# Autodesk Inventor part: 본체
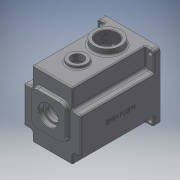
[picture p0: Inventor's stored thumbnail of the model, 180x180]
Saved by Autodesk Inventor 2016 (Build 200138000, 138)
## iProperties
Created: 2016-02
Part Number: 본체
Material: 알루미늄 6061
Document SubType Name: Modeling
Designer: mduedu
Density: 2.7 g/cm^3
Mass: 1348.73 g
Surface Area: 1142.22 cm^2
Volume: 499.531 cm^3
Appearance: 기본값
Author: mduedu
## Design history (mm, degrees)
sketch "스케치1"
  geometry: L1 (-47, -47)-(47, -47); L2 (47, -47)-(47, 63); L3 (47, 63)-(-47, 63); L4 (-47, 63)-(-47, -47); 2 further points
  constraints: 8 end point, 2 parallel, 1 horizontal, 1 midpoint, 1 perpendicular, 1 vertical alignment
  dimensions: "d0" = 94 distance of L2.end L3.end; "d155" = 110 distance of L1.end L2.end; "d156" = 47 distance from line of L1 point (0, 0)
extrude "돌출1" new body sketch "스케치1" distance "d2" = 130; taper "d3" = 0 deg
sketch "스케치3"
  geometry: C1 r 40 at (0, 0); 1 further point
  constraints: 1 centre point, 1 coincident
  dimensions: "d9" = 80 diameter of C1
extrude "돌출3" cut sketch "스케치3" distance "d11" = 121; taper "d12" = 0 deg
sketch "스케치4"
  geometry: C1 r 21 at (0, 11); 1 further point
  constraints: 1 centre point, 1 vertical alignment
  dimensions: "d13" = 21 radius of C1; "d15" = 11 distance of point (0, 0) C1.centre
extrude "돌출4" join sketch "스케치4" distance "d16" = 7; taper "d17" = 0 deg
sketch "스케치5"
  geometry: C1 r 15 at (0, -20); 1 further point
  constraints: 1 centre point, 1 vertical alignment
  dimensions: "d18" = 15 radius of C1; "d20" = 20 distance of point (0, 0) C1.centre
extrude "돌출5" join sketch "스케치5" distance "d21" = 7; taper "d22" = 0 deg
sketch "스케치6"
  geometry: L1 (-28, -17)-(28, -17); L2 (28, -17)-(28, 39); L3 (28, 39)-(-28, 39); L4 (-28, 39)-(-28, -17); L5 (-28, -17)-(28, 39); L6 (28, -17)-(-28, 39); C1 r 28 at (0, 11); A1 r 21 centre (0, 11) between (8.978, -7.984) and (-8.978, -7.984) reference; 1 further point
  constraints: 12 end point, 2 midpoint, 2 parallel, 2 tangent, 1 centre point, 1 coincident, 1 horizontal, 1 perpendicular
  dimensions: "d23" = 56 diameter of C1
extrude "돌출6" join sketch "스케치6" distance "d25" = 7; taper "d26" = -3 deg
hole "구멍1" diameter "d29" = 35; stored, may be unused: countersink angle "d33" = 90 deg, drill point angle "d35" = 0 deg; dims "d27" = 10, "d28" = 10, "d30" = 6, "d31" = 4, "d32" = 2, "d34" = 10
hole "구멍2" diameter "d38" = 22; stored, may be unused: countersink angle "d42" = 90 deg, drill point angle "d44" = 0 deg; dims "d36" = 10, "d37" = 10, "d39" = 6, "d40" = 4, "d41" = 2, "d43" = 7
hole "구멍3" diameter "d47" = 19; stored, may be unused: countersink angle "d51" = 90 deg, drill point angle "d53" = 0 deg; dims "d45" = 10, "d46" = 10, "d48" = 6, "d49" = 4, "d50" = 2, "d52" = 1
hole "구멍4" diameter "d56" = 32; stored, may be unused: countersink angle "d60" = 90 deg, drill point angle "d62" = 0 deg; dims "d57" = 6, "d58" = 4, "d59" = 2, "d61" = 8, "d220" = 10, "d221" = 10
hole "구멍5" diameter "d65" = 25; stored, may be unused: countersink angle "d69" = 90 deg, drill point angle "d71" = 0 deg; dims "d63" = 10, "d64" = 10, "d66" = 6, "d67" = 4, "d68" = 2, "d70" = 8
fillet "모깎기2" dims "d73" = 0.3
fillet "모깎기3" dims "d74" = 2
chamfer "모따기1" distance "d75" = 1; stored, may be unused: second distance "d76" = 2, angle "d77" = 45 deg
fillet "모깎기4" dims "d78" = 3
sketch "스케치16"
  geometry: L1 (-23, 32.726)-(23, 32.726); L2 (23, 32.726)-(23, 53); L3 (23, 53)-(-23, 53); L4 (-23, 53)-(-23, 32.726); L5 (-47, 63)-(47, 63) reference; 3 further points
  constraints: 8 end point, 2 parallel, 1 horizontal, 1 midpoint, 1 perpendicular, 1 vertical alignment, 2 other
  dimensions: "d160" = 46 distance of L2.end L3.end; "d163" = 10 distance between parallel lines of L3 L5
extrude "돌출15" cut sketch "스케치16" stored distance "d164" = 10; taper "d165" = 0 deg
fillet "모깎기5" dims "d79" = 2
fillet "모깎기15" dims "d166" = 5
sketch "스케치7"
  geometry: L1 (-23, 48)-(-23, 35.228) reference; L2 (23, 35.228)-(23, 48) reference; L3 (18, 53)-(-18, 53) reference; L4 (47, 63)-(47, -47) reference; L5 (47, -47)-(-47, -47) reference; L6 (-47, -47)-(-47, 63) reference; L7 (-47, 63)-(47, 63) reference; L8 (-26, 48)-(-26, 35.228); L9 (26, 35.228)-(26, 48); L10 (18, 56)-(-18, 56); C1 r 43 at (0, 0); A1 r 5 centre (-18, 48) between (-18, 53) and (-23, 48) reference; A2 r 5 centre (-28, 35.228) between (-24.889, 31.314) and (-23, 35.228) reference; A3 r 40 centre (0, 0) between (-24.889, 31.314) and (24.889, 31.314) reference; A4 r 5 centre (28, 35.228) between (23, 35.228) and (24.889, 31.314) reference; A5 r 5 centre (18, 48) between (23, 48) and (18, 53) reference; A6 r 8 centre (-18, 48) between (-18, 56) and (-26, 48); A7 r 2 centre (-28, 35.228) between (-26.756, 33.662) and (-26, 35.228); A8 r 43 centre (0, 0) between (-26.756, 33.662) and (26.756, 33.662); A9 r 2 centre (28, 35.228) between (26, 35.228) and (26.756, 33.662); A10 r 8 centre (18, 48) between (26, 48) and (18, 56); 1 further point
  constraints: 10 point on circle, 6 centre point, 6 end point, 1 coincident, 7 other
  dimensions: "d80" = 86 diameter of C1; "d167" = 3 distance between parallel lines of L3 L10
extrude "돌출7" cut sketch "스케치7" distance "d83" = 9; taper "d84" = 0 deg
sketch "스케치8" dims "d168" = 36
  geometry: L1 (-36, 4)-(-39.799, 4); L2 (-36, -4)-(-39.799, -4); A1 r 4 centre (-36, 0) between (-36, 4) and (-36, -4); A2 r 40 centre (0, 0) between (-24.889, 31.314) and (24.889, 31.314) reference; A3 r 40 centre (0, 0) between (-39.799, 4) and (-39.799, -4); 2 further points
  constraints: 5 point on circle, 4 end point, 2 centre point, 2 coincident, 2 horizontal alignment, 2 tangent, 1 horizontal, 1 parallel, 2 other
  dimensions: "d169" = 4 radius of A1
extrude "돌출9" join sketch "스케치8" stored distance "d89" = 9; taper "d90" = 0 deg
fillet "모깎기6" dims "d91" = 3.5
node "작업 평면1"
sketch "스케치9"
  geometry: L1 (47, 63)-(33, 63); L2 (33, 63)-(33, 30); L3 (33, 30)-(47, 30); L4 (47, 30)-(47, 63); L5 (47, 63)-(-47, 63) reference; L6 (47, -47)-(47, 63) reference; A1 r 40 centre (0, 0) between (-39.148, -8.214) and (39.148, -8.214) reference; 1 further point
  constraints: 8 end point, 2 parallel, 1 coincident, 1 horizontal, 1 perpendicular
  dimensions: "d95" = 33 distance from line of L2 point (0, 0); "d96" = 30 distance from line of L3 point (0, 0)
extrude "돌출10" cut sketch "스케치9" distance "d97" = 110; taper "d98" = 0 deg
extrude "돌출21" cut sketch "스케치9" stored distance "d217" = 10; taper "d218" = 0 deg
sketch "스케치11" dims "d20" = 20
  geometry: L1 (-40, -40)-(40, -40); L2 (40, -40)-(40, 56); L3 (40, 56)-(-40, 56); L4 (-40, 56)-(-40, -40); L5 (-47, -47)-(47, -47) reference; L6 (47, 63)-(-47, 63) reference; L7 (-47, 63)-(-47, -47) reference; C1 r 3.5 at (-40, 56); C2 r 3.5 at (40, 56); C3 r 3.5 at (40, -40); C4 r 3.5 at (-40, -40); 1 further point
  constraints: 8 end point, 4 centre point, 4 coincident, 3 equal radius, 2 parallel, 1 horizontal, 1 perpendicular
  dimensions: "d109" = 80 distance of L2.end L3.end; "d112" = 7 diameter of C1; "d157" = 7 distance from line of L1.start L5; "d158" = 7 distance between parallel lines of L6 L3; "d159" = 7 distance from line of L7 L3.end
extrude "돌출12" cut sketch "스케치11" stored distance "d113" = 63; taper "d114" = 0 deg
fillet "모깎기7" dims "d115" = 5, "d187" = 5
fillet "모깎기8" dims "d116" = 5
fillet "모깎기18" dims "d219" = 2
fillet "모깎기12" dims "d120" = 2
fillet "모깎기13" dims "d121" = 2
sketch "스케치12"
  geometry: 3 further points
  constraints: 2 horizontal alignment
hole "구멍6" sketch "스케치12" at (36, 0), (-36, 0) diameter "d122" = 3.242; stored, may be unused: countersink angle "d126" = 90 deg, drill point angle "d128" = 120 deg; dims "d123" = 7, "d124" = 4, "d125" = 2, "d127" = 9
fillet "모깎기14" dims "d147" = 10
chamfer "모따기4" distance "d151" = 1; stored, may be unused: second distance "d152" = 2, angle "d153" = 45 deg
sketch "스케치20"
  geometry: L1 (73, -12)-(73, -130) reference; L2 (84, -8)-(77, -8) reference; L3 (84, 0)-(84, -8) reference; L4 (84, 0)-(0, 0) reference; L5 (7, -8)-(0, -8) reference; L6 (11, -130)-(11, -12) reference; L7 (0, -8)-(0, 0) reference; L8 (73, -130)-(11, -130) reference; L9 (42, 0)-(42, -130); C1 r 10 at (42, -89); A1 r 4 centre (77, -12) between (77, -8) and (73, -12) reference; A2 r 4 centre (7, -12) between (11, -12) and (7, -8) reference
  constraints: 2 end point, 1 centre point, 1 midpoint, 1 point on line
  dimensions: "d189" = 20 diameter of C1; "d190" = 41 distance from line of C1.centre L8
extrude "돌출19" cut sketch "스케치20" stored distance "d191" = 10; taper "d192" = 0 deg
sketch "스케치18"
  geometry: C1 r 15 at (42, -89); C2 r 10 at (42, -89) reference; 1 further point
  constraints: 1 centre point, 1 concentric
  dimensions: "d174" = 30 diameter of C1
extrude "돌출17" join sketch "스케치18" distance "d175" = 5; taper "d176" = 0 deg
fillet "모깎기16" dims "d177" = 2
sketch "스케치19"
  geometry: C1 r 10 at (18, 80) reference; C2 r 15 at (18, 80); 1 further point
  constraints: 1 centre point, 1 coincident
  dimensions: "d178" = 30 diameter of C2
extrude "돌출18" cut sketch "스케치19" distance "d181" = 5; taper "d182" = 0 deg
chamfer "모따기5" distance "d183" = 0.5; stored, may be unused: second distance "d184" = 2, angle "d185" = 45 deg
sketch "스케치21"
  geometry: L1 (-12, 14)-(-130, 14) reference; L2 (-8, 0)-(-8, 10) reference; L3 (0, 0)-(0, 100) reference; L4 (-8, 100)-(0, 100) reference; L5 (-8, 74)-(-8, 100) reference; L6 (-130, 70)-(-12, 70) reference; L7 (-130, 14)-(-130, 70) reference; L8 (0, 0)-(-8, 0) reference; L9 (-130, 14)-(-130, 70) reference; L10 (27.4, 42)-(-164.4, 42) reference; A1 r 4 centre (-12, 74) between (-12, 70) and (-8, 74) reference; A2 r 4 centre (-12, 10) between (-8, 10) and (-12, 14) reference; 3 further points
  constraints: 1 coincident, 1 point on line, 1 other
  dimensions: "d222" = 65 distance from line of point (-65, 42) L9
feature "엠보싱2" sketch "스케치21" dims "d20" = 20, "d193" = 0.5, "d194" = 0
sketch "스케치22"
  geometry: L1 (73, -12)-(73, -130) reference; L2 (84, -8)-(77, -8) reference; L3 (84, 0)-(84, -8) reference; L4 (84, 0)-(0, 0) reference; L5 (7, -8)-(0, -8) reference; L6 (11, -130)-(11, -12) reference; L7 (0, -8)-(0, 0) reference; L8 (73, -130)-(11, -130) reference; L9 (42, -130)-(42, 0); C1 r 17 at (42, -89) reference; C2 r 22.5 at (42, -40); A1 r 4 centre (77, -12) between (77, -8) and (73, -12) reference; A2 r 4 centre (7, -12) between (11, -12) and (7, -8) reference
  constraints: 2 end point, 1 centre point, 1 midpoint, 1 point on line
  dimensions: "d195" = 45 diameter of C2; "d197" = 40 distance from line of C2.centre L4
extrude "돌출20" join sketch "스케치22" distance "d198" = 10; taper "d199" = 0 deg
fillet "모깎기17" dims "d200" = 3
hole "구멍7" diameter "d203" = 33.376; stored, may be unused: countersink angle "d207" = 90 deg, drill point angle "d209" = 118 deg; dims "d204" = 6, "d205" = 4, "d206" = 2, "d208" = 8, "d223" = 10, "d224" = 10
chamfer "모따기6" distance "d210" = 1; stored, may be unused: second distance "d211" = 2, angle "d212" = 45 deg
fillet "모깎기19" dims "d225" = 2
node "솔리드1"
pattern_circular "원형 패턴1" dims angle "d93" = 360 deg
mirror "대칭1"
mirror "대칭2"
node "투영된 루프1"
node "투영된 루프2"
node "투영된 루프3"
node "절단 모서리 투영3"
